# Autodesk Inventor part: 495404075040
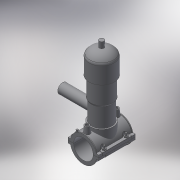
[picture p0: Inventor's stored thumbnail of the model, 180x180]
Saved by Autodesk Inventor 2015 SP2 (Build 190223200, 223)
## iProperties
Created: 2017-07
Part Number: 495404075040
Material: Generic
Description: PLASSON TAPPING VALVE 75-40
Document SubType Name: Modeling
Designer: KIM
Density: 1 g/cm^3
Appearance: Default
Author: KIM
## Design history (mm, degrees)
derived "495404-4954S4.ipt"
feature "Solid1::495404-4954S4.ipt"
feature "Solid2::495404-4954S4.ipt"
tag "TaggingFeature1"
body "Solid1"
body "Solid2"
other parameters: "d_" = 75, "B_" = 117, "H_" = 137, "L_" = 118, "d_t" = 6, "H_1" = 46, "H_2" = 244, "d148" = 1.125, "d160" = 1.125, "d169" = 3, "d192" = 6.8, "d228" = 32, "d0" = 75, "d2" = 117, "d3" = 18.75, "d4" = 118, "d5" = 0, "d6" = 0.1, "d8" = 0, "d19" = 6, "d20" = 6, "d21" = 70.8, "d23" = 0, "d24" = 35.4, "d26" = 0, "d27" = 3, "d28" = 3, "d29" = 3, "d30" = 25, "d31" = 6, "d32" = 0, "d33" = 0, "d34" = 0.6, "d40" = 50.7, "d47" = 94.75, "d70" = 15, "d72" = 0, "d73" = 6, "d75" = 5, "d76" = 0, "d77" = 3.75, "d78" = 67.5, "d79" = 15, "d80" = 47.2, "d82" = 5 deg, "d84" = 4, "d85" = 14, "d86" = 0, "d87" = 3, "d88" = 0, "d89" = 1, "d90" = 1, "d91" = 94.4, "d92" = 0, "d93" = 0.5, "d94" = 39.47368, "d96" = 100.425, "d97" = 2.36, "d98" = 0, "d120" = 140 deg, "d121" = 24.228, "d122" = 20 deg, "d123" = 195, "d124" = 58.5, "d126" = 0, "d143" = 77.25, "d145" = 17.30769, "d149" = 1.125, "d150" = 19.03846, "d153" = 118, "d154" = 0, "d156" = 48.75, "d157" = 160 deg, "d159" = 4.5, "d161" = 1.125, "d162" = 70.8, "d163" = 0, "d164" = 37.5, "d167" = 7.5, "d168" = 47.56098, "d170" = 3, "d172" = 0, "d173" = 1, "d175" = 37.5, "d176" = 20 deg, "d177" = 5.25, "d178" = 22.5, "d180" = 0, "d183" = 9, "d184" = 4.2, "d185" = 38.35, "d186" = 38.35, "d187" = 48.75, "d188" = 6.75, "d189" = 5.25, "d190" = 0, "d191" = 73.125, "d193" = 6.8, "d194" = 2.95, "d195" = 90 deg, "d197" = 0, "d199" = 0, "d205" = 14.64, "d206" = 81.33333, "d207" = 244, "d208" = 224.48, "d209" = 207.4, "d210" = 200.08, "d211" = 146.4, "d212" = 85.4, "d213" = 65.88, "d214" = 73.2, "d216" = 19.52, "d217" = 70.76, "d218" = 80.52, "d220" = 75, "d222" = 0, "d223" = 97.5, "d224" = 137, "d225" = 46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
